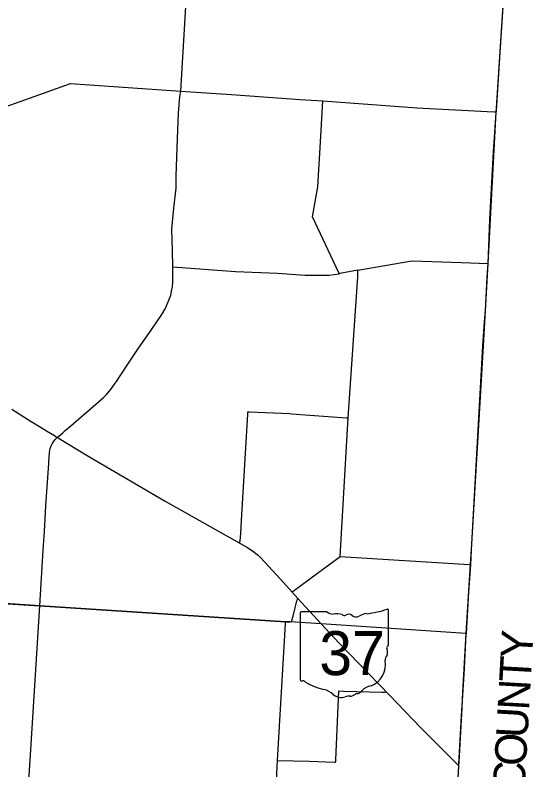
# Model space of a CAD drawing. Extents: x 1729596 to 1925846, y 659247 to 911751.
# Drawn here: x 1882614 to 1898982, y 797404 to 821273 of the extents above; entities that cross this region are included whole.
import ezdxf

# ---------------------------------------------------------------- set-up
doc = ezdxf.new("R2010")
doc.units = 0
for name, color, linetype in [('GM_X_Adjacent_County_Text', 7, 'Continuous'), ('GM_X_County', 7, 'Continuous'), ('GM_X_County_Road', 7, 'Continuous'), ('GM_X_State_Route', 7, 'Continuous'), ('GM_X_State_Shield', 7, 'Continuous'), ('GM_X_Township', 7, 'Continuous'), ('GM_X_Township_Road', 7, 'Continuous')]:
    doc.layers.add(name, color=color, linetype=linetype)

msp = doc.modelspace()

# ---------------------------------------------------------------- linework, layer by layer
at = {"layer": 'GM_X_County'}
msp.add_lwpolyline([(1898045, 821739), (1897825, 818330), (1897815, 818218), (1897557, 813421), (1897406, 810815), (1897032, 804371), (1897004, 803896), (1896867, 801714), (1896762, 799856), (1896723, 799168), (1896641, 797645), (1896629, 797539), (1896376, 792790)], dxfattribs=at)
at = {"layer": 'GM_X_County_Road'}
for points in [[(1897822, 818179), (1897829, 818255), (1897948, 820090), (1898048, 821704), (1898128, 823007), (1898166, 823650), (1898353, 826531), (1898388, 827089), (1898531, 829465)], [(1883945, 807913), (1884121, 808063), (1884192, 808137), (1884375, 808287), (1884615, 808499), (1884999, 808823), (1885413, 809183), (1885505, 809275), (1885580, 809356), (1885631, 809420), (1885760, 809600), (1885818, 809685), (1885938, 809865), (1886242, 810330), (1886511, 810739), (1886917, 811312), (1887249, 811810), (1887355, 811986), (1887375, 812027), (1887424, 812129), (1887477, 812258), (1887533, 812417), (1887573, 812593), (1887586, 812678), (1887600, 812854), (1887602, 813023), (1887597, 813309), (1887587, 813833), (1887573, 814503), (1887636, 815166), (1887701, 815803), (1887705, 816183), (1887748, 817374), (1887780, 818173), (1887818, 818696), (1887858, 818871), (1888113, 823336)], [(1871277, 818480), (1872206, 818406), (1875525, 818156), (1880663, 817814), (1881619, 818131), (1884362, 819111), (1887858, 818871), (1889457, 818761), (1891623, 818604), (1892346, 818560), (1895326, 818344), (1897532, 818224), (1897769, 818211), (1897801, 818204), (1897822, 818179)], [(1897564, 813416), (1897624, 814812), (1897737, 816947), (1897822, 818179)], [(1896877, 801685), (1896878, 801713), (1896961, 803039), (1897015, 803890), (1897038, 804349), (1897401, 810812), (1897452, 811576), (1897482, 811930), (1897540, 812982), (1897564, 813416)], [(1896641, 797536), (1896646, 797601), (1896729, 799110), (1896778, 799931), (1896816, 800595), (1896842, 801059), (1896877, 801685)], [(1896288, 791046), (1896384, 792784), (1896550, 795738), (1896641, 797536)]]:
    msp.add_lwpolyline(points, dxfattribs=at)
at = {"layer": 'GM_X_State_Route'}
for points in [[(1882507, 808811), (1883124, 808426), (1883245, 808350), (1883608, 808131), (1883859, 807974), (1883945, 807913)], [(1883681, 807137), (1883700, 807443), (1883727, 807565), (1883754, 807653), (1883783, 807713), (1883829, 807777), (1883885, 807848), (1883945, 807913)], [(1883945, 807913), (1884008, 807879), (1884894, 807348), (1887358, 805901), (1889702, 804583), (1889965, 804433), (1890068, 804367), (1890146, 804309), (1890221, 804252), (1890297, 804190), (1890369, 804123), (1890999, 803432), (1891373, 803023), (1891553, 802825), (1892288, 802025), (1892862, 801410), (1894115, 800116), (1894249, 799980), (1894338, 799884), (1894447, 799772), (1895444, 798735), (1896641, 797536)], [(1882720, 791504), (1882978, 795867), (1883003, 796429), (1883088, 797714), (1883392, 802588), (1883500, 804351), (1883543, 804938), (1883588, 805754), (1883679, 807097), (1883681, 807137)]]:
    msp.add_lwpolyline(points, dxfattribs=at)
at = {"layer": 'GM_X_State_Shield'}
for p, q in [((1891630, 802365), (1891630, 800251)), ((1891630, 802365), (1891630, 800251)), ((1892472, 802401), (1891657, 802401)), ((1892472, 802401), (1891657, 802401)), ((1894414, 801348), (1894414, 802453)), ((1894414, 801348), (1894414, 802453)), ((1894414, 801348), (1894414, 801348)), ((1894414, 801348), (1894414, 801348))]:
    msp.add_line(p, q, dxfattribs=at)
for centre, radius, start, end in [((1891661, 802369), 32.3, 98.1301, 188.1301), ((1891661, 802369), 32.3, 98.1301, 188.1301), ((1892667, 802646), 313, 231.6195, 271.1119), ((1892667, 802646), 313, 231.6195, 271.1119), ((1892770, 801215), 1123, 80.4867, 94.9883), ((1892770, 801215), 1123, 80.4867, 94.9883), ((1893025, 802380), 90.3, 219.7921, 297.1024), ((1893025, 802380), 90.3, 219.7921, 297.1024), ((1893158, 802136), 188, 54.4667, 119.1411), ((1893158, 802136), 188, 54.4667, 119.1411), ((1893400, 802471), 226, 233.8562, 294.8282), ((1893400, 802471), 226, 233.8562, 294.8282), ((1893799, 801756), 594, 97.3462, 120.7689), ((1893799, 801756), 594, 97.3462, 120.7689), ((1893422, 805282), 2953, 275.8445, 288.9065), ((1893422, 805282), 2953, 275.8445, 288.9065), ((1894383, 802458), 31, 351.8621, 97.738), ((1894383, 802458), 31, 351.8621, 97.738), ((1894407, 801267), 48, 107.944, 210.337), ((1894407, 801267), 48, 107.944, 210.337), ((1894381, 801344), 33.2, 289.6038, 7.7341), ((1894381, 801344), 33.2, 289.6038, 7.7341), ((1894102, 801127), 288, 340.033, 23.6496), ((1894102, 801127), 288, 340.033, 23.6496), ((1893587, 800745), 739, 292.3089, 8.9858), ((1893587, 800745), 739, 292.3089, 8.9858), ((1894525, 800885), 210, 136.8065, 186.9296), ((1894525, 800885), 210, 136.8065, 186.9296), ((1891662, 800247), 32.5, 171.9584, 258.3066), ((1891662, 800247), 32.5, 171.9584, 258.3066), ((1891667, 800463), 248, 267.339, 280.6039), ((1891667, 800463), 248, 267.339, 280.6039), ((1891717, 800129), 89.5, 29.7484, 93.2717), ((1891717, 800129), 89.5, 29.7484, 93.2717), ((1892848, 802028), 2132, 240.4129, 257.1985), ((1892848, 802028), 2132, 240.4129, 257.1985), ((1892212, 799302), 667, 47.1842, 75.836), ((1892212, 799302), 667, 47.1842, 75.836), ((1893386, 800047), 239, 282.8732, 323.2771), ((1893386, 800047), 239, 282.8732, 323.2771), ((1893899, 799658), 404, 94.4031, 142.5768), ((1893899, 799658), 404, 94.4031, 142.5768), ((1892934, 800119), 423, 230.7004, 286.2918), ((1892934, 800119), 423, 230.7004, 286.2918), ((1893178, 799388), 348, 85.6951, 111.2099), ((1893178, 799388), 348, 85.6951, 111.2099), ((1893209, 799961), 226, 268.777, 315.5493), ((1893209, 799961), 226, 268.777, 315.5493), ((1893413, 799756), 63.5, 65.7517, 132.6484), ((1893413, 799756), 63.5, 65.7517, 132.6484)]:
    msp.add_arc(centre, radius, start, end, dxfattribs=at)
at = {"layer": 'GM_X_Township'}
msp.add_lwpolyline([(1896867, 801714), (1892288, 802025), (1891297, 802083), (1891221, 802088), (1891165, 802089), (1883392, 802588), (1877369, 802994), (1870008, 803514), (1870309, 808163), (1870779, 814239), (1870903, 816053), (1870933, 816495), (1870943, 816996), (1871003, 817857), (1871065, 818497), (1871124, 819057), (1871199, 820179), (1871965, 831096)], dxfattribs=at)
at = {"layer": 'GM_X_Township_Road'}
for points in [[(1892877, 813100), (1892856, 813096), (1892847, 813127), (1892013, 814894), (1892187, 815844), (1892275, 817450), (1892346, 818560)], [(1893446, 813209), (1895152, 813500), (1896723, 813446), (1897564, 813416)], [(1887597, 813309), (1889585, 813162), (1890912, 813114), (1891786, 813054), (1892545, 813045), (1892856, 813096)], [(1891373, 803023), (1891387, 803039), (1891405, 803057), (1892171, 803626), (1892889, 804151), (1893142, 808538), (1893444, 812998), (1893450, 813114), (1893446, 813209)], [(1893446, 813209), (1892877, 813100)], [(1889702, 804583), (1889716, 804612), (1889727, 804647), (1889746, 804884), (1889770, 805286), (1889966, 808657), (1889971, 808727), (1890002, 808726), (1890019, 808725)], [(1890019, 808725), (1891290, 808671), (1891349, 808669), (1893087, 808542), (1893142, 808538)], [(1892889, 804151), (1896968, 803896), (1897015, 803890)], [(1877369, 802994), (1880691, 802757), (1883392, 802588)], [(1891312, 802088), (1891337, 802094), (1891347, 802102), (1891354, 802110), (1891365, 802128), (1891402, 802264), (1891525, 802755), (1891537, 802794), (1891544, 802811), (1891553, 802825)], [(1883392, 802588), (1891165, 802089)], [(1890439, 788430), (1890599, 791825), (1890663, 793067), (1890758, 794790), (1890789, 795400), (1890905, 797697), (1891157, 802023), (1891165, 802089), (1891207, 802088)], [(1891207, 802088), (1891221, 802088), (1891297, 802083), (1891312, 802088)], [(1890905, 797697), (1891923, 797682), (1892705, 797649), (1892735, 797650), (1892749, 797657), (1892754, 797681), (1892755, 797718), (1892849, 799904), (1892999, 799898)], [(1892999, 799898), (1893021, 799897), (1894207, 799861), (1894280, 799859), (1894312, 799865), (1894338, 799884)]]:
    msp.add_lwpolyline(points, dxfattribs=at)

# ---------------------------------------------------------------- texts
at = {"layer": 'GM_X_Adjacent_County_Text'}
for s, rotation, p in [('Y', 86.7665, (1898954, 800905)), ('T', 86.7674, (1898911, 800158)), ('N', 86.7675, (1898862, 799275)), ('U', 86.7602, (1898812, 798392)), ('O', 86.7321, (1898761, 797508)), ('C', 86.4487, (1898710, 796690))]:
    msp.add_text(s, height=1000, rotation=rotation, dxfattribs=at).set_placement(p)
at = {"layer": 'GM_X_State_Shield'}
msp.add_text('37', height=1392.2, dxfattribs=at).set_placement((1892230, 800400))
msp.add_text('37', height=1392.2, dxfattribs=at).set_placement((1892230, 800400))

doc.saveas('drawing.dxf')
